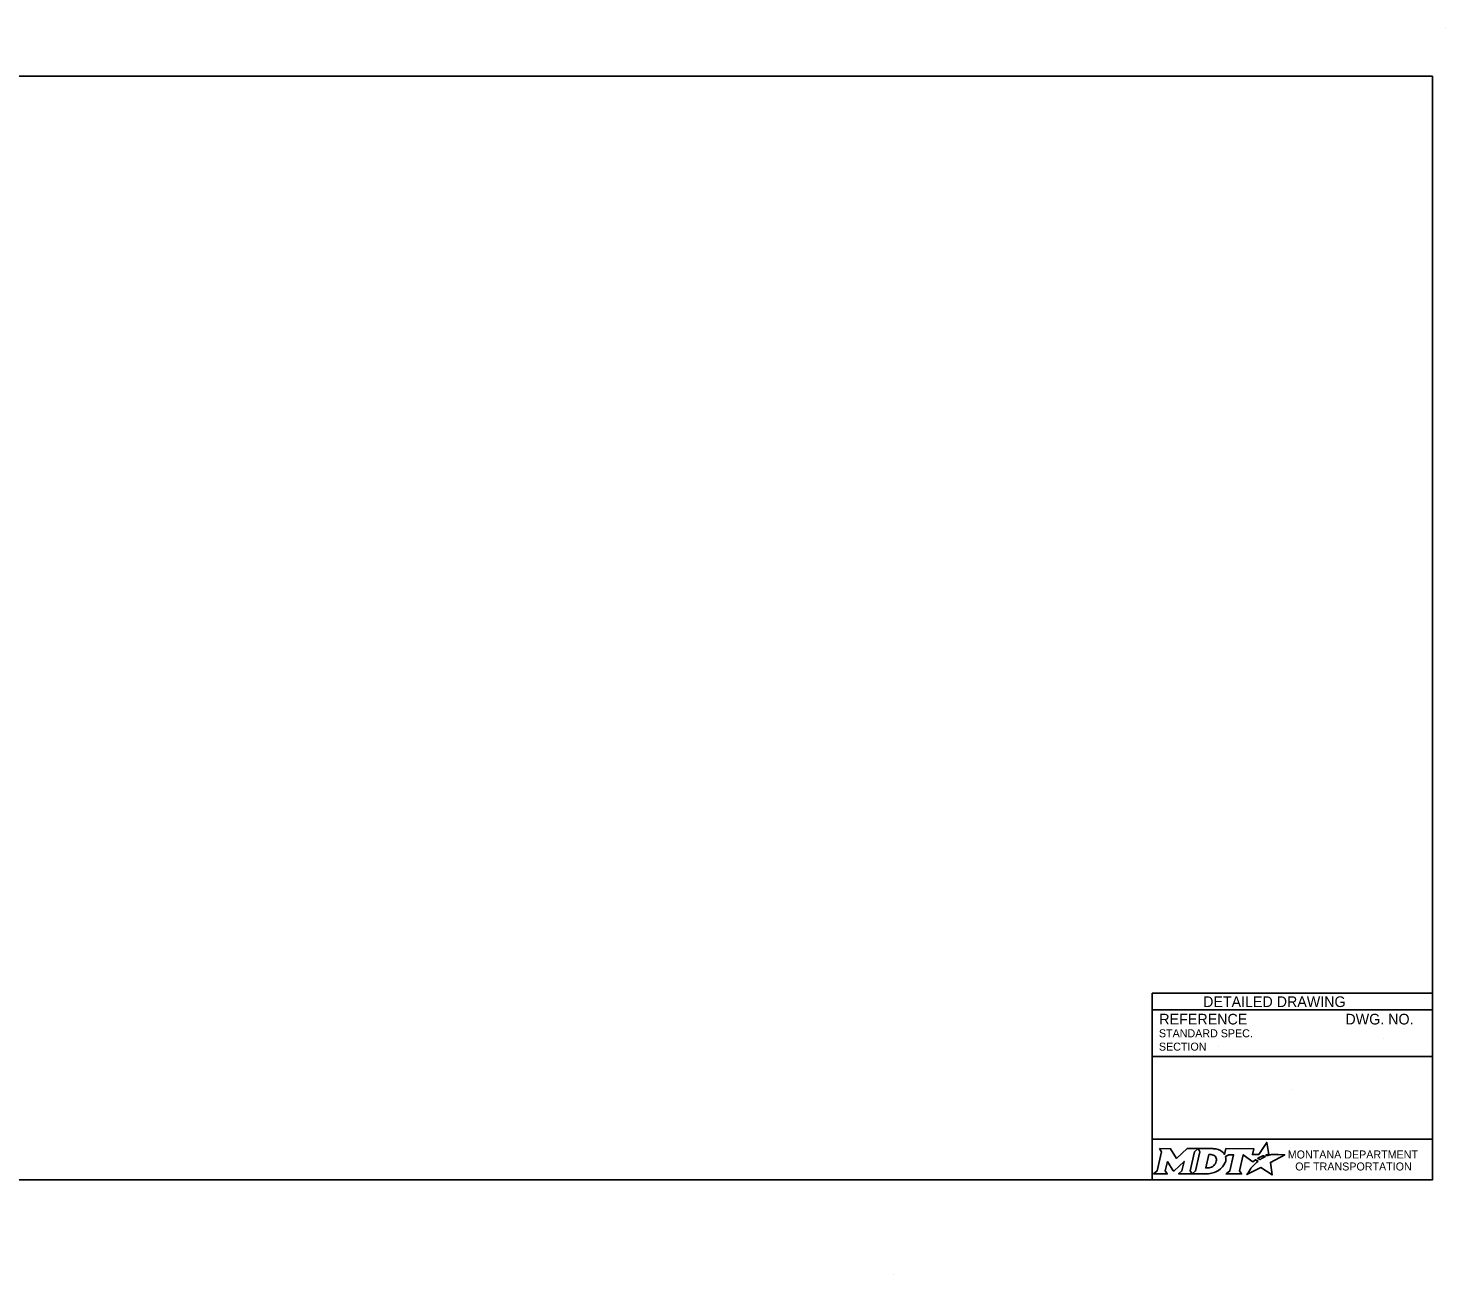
# Model space of a CAD drawing. Extents: x 49991 to 81321, y 49988 to 50028.
# Drawn here: x 50010.41 to 50021.04, y 49999.18 to 50008.52 of the extents above; entities that cross this region are included whole.
import ezdxf

# ---------------------------------------------------------------- set-up
doc = ezdxf.new("R2010")
doc.units = 0
for name, color, linetype in [('Default', 7, 'Continuous'), ('Level 1', 7, 'Continuous'), ('Level 4', 7, 'Continuous')]:
    doc.layers.add(name, color=color, linetype=linetype)

msp = doc.modelspace()

# ---------------------------------------------------------------- linework, layer by layer
at = {"layer": 'Default'}
for points in [[(50018.893, 50000.121), (50018.907, 50000.097), (50018.874, 49999.954), (50018.848, 49999.931), (50018.95, 49999.931), (50018.936, 49999.954), (50018.952, 50000.024), (50018.996, 49999.955), (50019.002, 49999.955), (50019.077, 50000.025), (50019.06, 49999.954), (50019.035, 49999.932), (50019.137, 49999.932), (50019.123, 49999.955), (50019.156, 50000.097)], [(50019.156, 50000.097), (50019.182, 50000.121), (50019.099, 50000.121), (50019.02, 50000.048), (50018.975, 50000.12), (50018.893, 50000.121)], [(50019.295, 50000.121), (50019.182, 50000.121), (50019.196, 50000.098), (50019.163, 49999.954), (50019.137, 49999.932), (50019.248, 49999.932)], [(50019.7, 50000.068), (50019.69, 50000.074), (50019.702, 50000.076), (50019.713, 50000.078), (50019.696, 50000.168), (50019.636, 50000.077), (50019.589, 50000.076), (50019.599, 50000.12), (50019.39, 50000.121), (50019.38, 50000.078), (50019.374, 50000.086)], [(50019.319, 50000.034), (50019.318, 50000.026), (50019.315, 50000.017), (50019.311, 50000.008), (50019.305, 50000.001), (50019.299, 49999.994), (50019.291, 49999.988), (50019.282, 49999.983), (50019.273, 49999.979), (50019.264, 49999.977), (50019.255, 49999.976), (50019.239, 49999.976), (50019.263, 50000.076), (50019.279, 50000.076), (50019.286, 50000.075), (50019.294, 50000.073), (50019.301, 50000.07), (50019.307, 50000.066), (50019.311, 50000.061), (50019.315, 50000.055), (50019.318, 50000.049), (50019.319, 50000.042), (50019.32, 50000.038), (50019.319, 50000.034)], [(50019.387, 50000.062), (50019.411, 50000.075), (50019.448, 50000.075), (50019.42, 49999.954), (50019.392, 49999.931), (50019.508, 49999.931), (50019.491, 49999.954), (50019.52, 50000.075), (50019.591, 50000.023), (50019.612, 50000.038), (50019.632, 50000.027)], [(50019.576, 49999.971), (50019.561, 49999.947), (50019.556, 49999.939), (50019.55, 49999.931), (50019.548, 49999.926), (50019.653, 49999.979), (50019.737, 49999.924), (50019.724, 50000.017), (50019.831, 50000.075), (50019.782, 50000.076), (50019.751, 50000.077), (50019.731, 50000.077), (50019.724, 50000.075), (50019.719, 50000.074), (50019.711, 50000.072), (50019.7, 50000.068)], [(50019.59, 49999.987), (50019.59, 49999.987)], [(50019.65, 50000.04), (50019.648, 50000.039), (50019.629, 50000.048), (50019.639, 50000.054), (50019.644, 50000.056), (50019.652, 50000.06), (50019.658, 50000.063), (50019.666, 50000.066), (50019.673, 50000.068), (50019.685, 50000.061), (50019.681, 50000.059), (50019.676, 50000.056), (50019.672, 50000.054), (50019.667, 50000.051), (50019.665, 50000.05), (50019.662, 50000.049), (50019.66, 50000.047), (50019.658, 50000.046), (50019.655, 50000.044), (50019.652, 50000.042), (50019.65, 50000.04)], [(50019.293, 49999.939), (50019.302, 49999.942), (50019.315, 49999.947), (50019.335, 49999.958)]]:
    msp.add_lwpolyline(points, dxfattribs=at)
for centre, radius, start, end in [((50019.274, 50000.059), 0.118, 300.9103, 339.1383), ((50019.319, 50000.042), 0.0709, 339.5329, 15.8582)]:
    msp.add_arc(centre, radius, start, end, dxfattribs=at)
for centre, major_axis, ratio, start_param, end_param in [((50019.293, 50000.073), (0.0834, -0.0037), 0.568097, 0.61298, 1.570796), ((50019.349, 50000.081), (0.0361, -0.0295), 0.469099, 1.225588, 1.570796), ((50019.583, 49999.979), (-0.00694, -0.00806), 0.008222, 0, 3.137361), ((50019.6, 49999.997), (-0.0098, -0.0102), 0.016458, 3.141593, 6.279097), ((50019.621, 50000.017), (-0.0112, -0.0097), 0.021651, 3.157348, 6.283185), ((50019.248, 50000.08), (0, 0.148), 0.987302, 3.139398, 3.456847)]:
    msp.add_ellipse(centre, major_axis=major_axis, ratio=ratio, start_param=start_param, end_param=end_param, dxfattribs=at)
at = {"layer": 'Level 1'}
for p, q in [((50021.038, 50008.524), (50021.038, 50008.524)), ((50016.9, 49999.176), (50016.9, 49999.176))]:
    msp.add_line(p, q, dxfattribs=at)
msp.add_lwpolyline([(50020.938, 50008.165), (50009.737, 50008.165), (50009.737, 49999.886), (50020.938, 49999.886)], close=True, dxfattribs=at)
at = {"layer": 'Level 4'}
for p, q in [((50020.938, 50001.286), (50018.838, 50001.286)), ((50018.838, 50001.286), (50018.838, 49999.886)), ((50020.938, 50001.161), (50018.838, 50001.161)), ((50020.574, 50000.946), (50020.574, 50000.946)), ((50019.332, 50000.886), (50019.332, 50000.886)), ((50020.938, 50000.811), (50018.838, 50000.811)), ((50019.888, 50000.562), (50019.888, 50000.562)), ((50020.938, 50000.193), (50018.838, 50000.193))]:
    msp.add_line(p, q, dxfattribs=at)

# ---------------------------------------------------------------- texts
at = {"layer": 'Default'}
for s, p in [('MONTANA DEPARTMENT', (50019.854, 50000.047)), ('OF TRANSPORTATION', (50019.91, 49999.957))]:
    msp.add_text(s, height=0.06, dxfattribs=at).set_placement(p)
at = {"layer": 'Level 4'}
for s, height, p in [('DETAILED DRAWING', 0.0799, (50019.219, 50001.183)), ('REFERENCE', 0.08, (50018.891, 50001.052)), ('DWG. NO.', 0.08, (50020.286, 50001.052)), ('STANDARD SPEC.', 0.06, (50018.888, 50000.956)), ('SECTION', 0.06, (50018.888, 50000.856))]:
    msp.add_text(s, height=height, dxfattribs=at).set_placement(p)

doc.saveas('drawing.dxf')
